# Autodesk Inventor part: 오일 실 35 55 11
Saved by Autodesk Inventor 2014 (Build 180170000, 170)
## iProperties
Created: 2025-06
Part Number: 오일 실 35 55 11
Material: 일반
Document SubType Name: Modeling
Designer: dg
Density: 1 g/cm^3
Appearance: 기본값
Author: dg
Author: jhkim
Description: 오일 실 - 비스프링, 조립 GA
Creation Date: 2025-05-23
Sending System: Autodesk Inventor 2026
Preprocessor: ST-DEVELOPER v20.1
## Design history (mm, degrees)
node "오일 실 35 55 111"
body "Solid1"
node "기준1"
